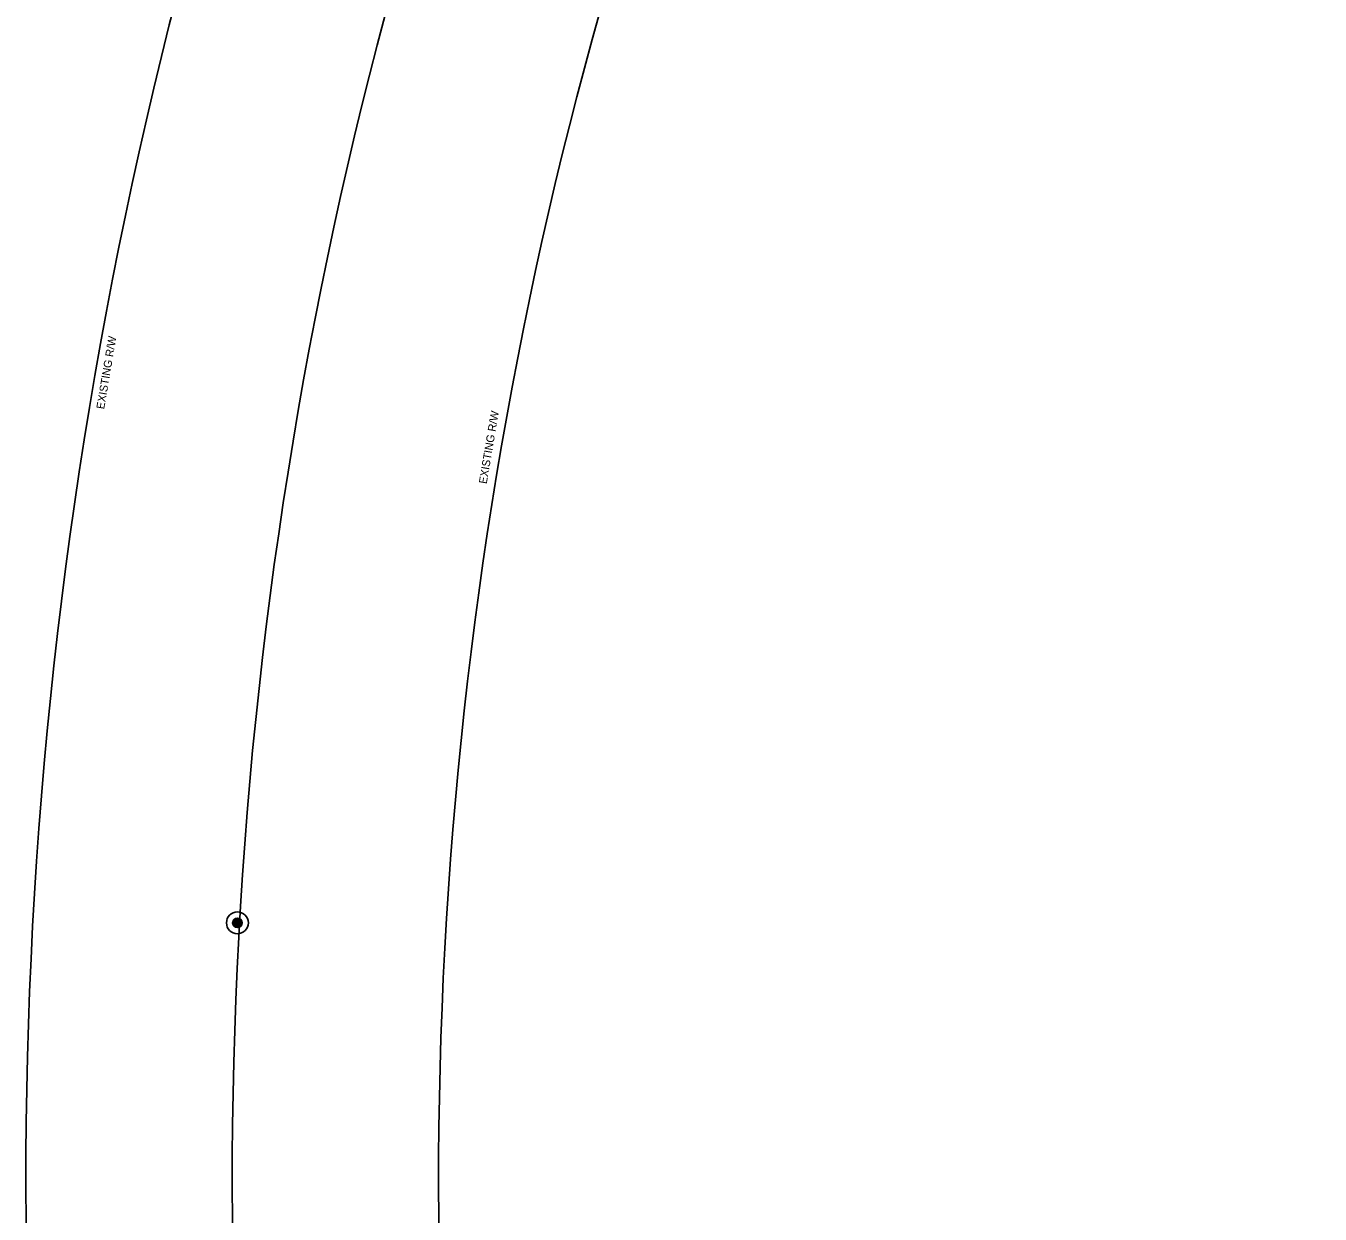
# Model space of a CAD drawing. Extents: x 1398271 to 1401121, y 1018936 to 1022764.
# Drawn here: x 1399691.9 to 1399898.8, y 1020426.2 to 1020616.3 of the extents above; entities that cross this region are included whole.
import ezdxf

# ---------------------------------------------------------------- set-up
doc = ezdxf.new("R2010")
doc.units = 0
for name, color, linetype in [('RD_EX_DV_PropPin', 7, 'Continuous'), ('RD_EX_RW', 7, 'Continuous'), ('RD_EX_RW_TX', 7, 'Continuous'), ('RD_HC_Cl', 7, 'Continuous'), ('RD_SMD_Locator', 7, 'Continuous')]:
    doc.layers.add(name, color=color, linetype=linetype)

msp = doc.modelspace()

# ---------------------------------------------------------------- linework, layer by layer
at = {"layer": 'RD_EX_DV_PropPin'}
for p, q in [((1399724.97, 1020472.64), (1399724.97, 1020473.03)), ((1399725.01, 1020472.54), (1399725.01, 1020473.13)), ((1399725.04, 1020472.47), (1399725.04, 1020473.2)), ((1399725.08, 1020472.41), (1399725.08, 1020473.26)), ((1399725.11, 1020472.36), (1399725.11, 1020473.31)), ((1399725.15, 1020472.32), (1399725.15, 1020473.35)), ((1399725.18, 1020472.28), (1399725.18, 1020473.39)), ((1399725.22, 1020472.25), (1399725.22, 1020473.42)), ((1399725.25, 1020472.23), (1399725.25, 1020473.44)), ((1399725.29, 1020472.2), (1399725.29, 1020473.47)), ((1399725.32, 1020472.18), (1399725.32, 1020473.49)), ((1399725.36, 1020472.16), (1399725.36, 1020473.51)), ((1399725.39, 1020472.14), (1399725.39, 1020473.53)), ((1399725.43, 1020472.13), (1399725.43, 1020473.54)), ((1399725.46, 1020472.11), (1399725.46, 1020473.56)), ((1399725.5, 1020472.1), (1399725.5, 1020473.57)), ((1399725.53, 1020472.09), (1399725.53, 1020473.58)), ((1399725.57, 1020472.09), (1399725.57, 1020473.58)), ((1399725.6, 1020472.08), (1399725.6, 1020473.59)), ((1399725.64, 1020472.08), (1399725.64, 1020473.59)), ((1399725.67, 1020472.07), (1399725.67, 1020473.6)), ((1399725.71, 1020472.07), (1399725.71, 1020473.6)), ((1399725.74, 1020472.07), (1399725.74, 1020473.6)), ((1399725.78, 1020472.08), (1399725.78, 1020473.59)), ((1399725.81, 1020472.08), (1399725.81, 1020473.59)), ((1399725.85, 1020472.09), (1399725.85, 1020473.58)), ((1399725.88, 1020472.09), (1399725.88, 1020473.58)), ((1399725.92, 1020472.1), (1399725.92, 1020473.57)), ((1399725.95, 1020472.11), (1399725.95, 1020473.56)), ((1399725.99, 1020472.13), (1399725.99, 1020473.54)), ((1399726.02, 1020472.14), (1399726.02, 1020473.53)), ((1399726.06, 1020472.16), (1399726.06, 1020473.51)), ((1399726.09, 1020472.18), (1399726.09, 1020473.49)), ((1399726.13, 1020472.2), (1399726.13, 1020473.47)), ((1399726.16, 1020472.23), (1399726.16, 1020473.44)), ((1399726.2, 1020472.25), (1399726.2, 1020473.42)), ((1399726.23, 1020472.28), (1399726.23, 1020473.39)), ((1399726.27, 1020472.32), (1399726.27, 1020473.35)), ((1399726.3, 1020472.36), (1399726.3, 1020473.31)), ((1399726.34, 1020472.41), (1399726.34, 1020473.26)), ((1399726.37, 1020472.47), (1399726.37, 1020473.2)), ((1399726.41, 1020472.54), (1399726.41, 1020473.13)), ((1399726.44, 1020472.64), (1399726.44, 1020473.03))]:
    msp.add_line(p, q, dxfattribs=at)
for radius in [1.75, 0.761]:
    msp.add_circle((1399725.71, 1020472.84), radius, dxfattribs=at)
at = {"layer": 'RD_EX_RW'}
for radius in [754.84, 688.84]:
    msp.add_arc((1400446.73, 1020431.86), radius, 142.68944, 193.74255, dxfattribs=at)
at = {"layer": 'RD_HC_Cl'}
msp.add_arc((1400446.73, 1020431.86), 721.84, 142.68944, 193.74255, dxfattribs=at)
at = {"layer": 'RD_SMD_Locator'}
msp.add_circle((1399725.71, 1020472.84), 0.15, dxfattribs=at)

# ---------------------------------------------------------------- texts
at = {"layer": 'RD_EX_RW_TX'}
for p in [(1399704.4, 1020554.95), (1399765.57, 1020543)]:
    msp.add_text('EXISTING R/W', height=1.28, rotation=80.3796, dxfattribs=at).set_placement(p)

doc.saveas('drawing.dxf')
